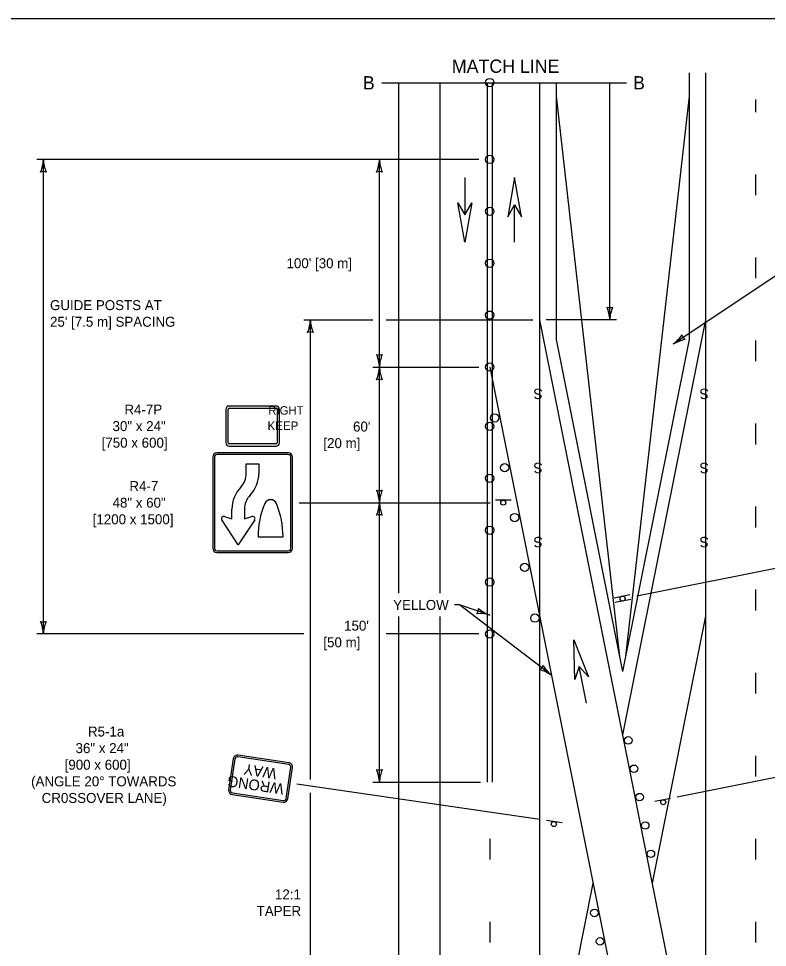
# Model space of a CAD drawing. Extents: x 49991.4 to 50021, y 49987.6 to 50011.4.
# Drawn here: x 50003.75 to 50008.26, y 49993.41 to 49999 of the extents above; entities that cross this region are included whole.
import ezdxf

# ---------------------------------------------------------------- set-up
doc = ezdxf.new("R2010")
doc.units = 0
for name, color, linetype in [('Level 1', 7, 'Continuous'), ('Level 2', 7, 'Continuous'), ('Level 3', 7, 'Continuous'), ('Level 6', 7, 'Continuous')]:
    doc.layers.add(name, color=color, linetype=linetype)

msp = doc.modelspace()

# ---------------------------------------------------------------- linework, layer by layer
at = {"layer": 'Level 1'}
for p, q in [((50007.7852, 49998.6725), (50007.7852, 49997.0679)), ((50007.8852, 49998.6725), (50007.8852, 49997.1857)), ((50006.0352, 49998.6125), (50006.0352, 49995.5387)), ((50006.2852, 49998.6125), (50006.2852, 49995.5387)), ((50006.5702, 49998.6125), (50006.5702, 49998.1511)), ((50006.6002, 49998.6125), (50006.6002, 49998.1511)), ((50006.8852, 49998.6125), (50006.8852, 49997.1857)), ((50006.9852, 49998.6125), (50006.9852, 49997.0679)), ((50006.9852, 49998.5323), (50007.3672, 49995.1581)), ((50007.7852, 49998.5323), (50007.4032, 49995.1581)), ((50008.1852, 49998.5125), (50008.1852, 49998.4357)), ((50006.5702, 49998.1511), (50006.5702, 49994.4011)), ((50006.6002, 49998.1511), (50006.6002, 49994.4011)), ((50006.4351, 49998.0424), (50006.4351, 49997.8166)), ((50006.4353, 49998.0424), (50006.4353, 49997.8166)), ((50008.1852, 49998.0607), (50008.1852, 49997.9357)), ((50006.735, 49997.6524), (50006.735, 49997.8782)), ((50006.7352, 49997.6524), (50006.7352, 49997.8782)), ((50008.1852, 49997.5607), (50008.1852, 49997.4357)), ((50006.8852, 49997.1857), (50006.8852, 49995.4011)), ((50006.8852, 49997.1855), (50008.1852, 49990.6855)), ((50007.8852, 49997.1857), (50007.3852, 49994.6857)), ((50007.8852, 49997.1857), (50007.8852, 49995.4012)), ((50006.9852, 49997.0679), (50007.3852, 49995.0679)), ((50007.7852, 49997.0679), (50007.3852, 49995.0679)), ((50008.1852, 49997.0607), (50008.1852, 49996.9357)), ((50006.5852, 49996.9011), (50007.8852, 49990.4009)), ((50004.9959, 49996.6463), (50004.9959, 49996.4447)), ((50005.0094, 49996.4447), (50005.0094, 49996.6463)), ((50005.2983, 49996.6665), (50005.0161, 49996.6665)), ((50005.0161, 49996.653), (50005.2983, 49996.653)), ((50005.305, 49996.6463), (50005.305, 49996.4447)), ((50005.3185, 49996.4447), (50005.3185, 49996.6463)), ((50008.1852, 49996.5607), (50008.1852, 49996.4357)), ((50005.2983, 49996.438), (50005.0161, 49996.438)), ((50005.0161, 49996.4245), (50005.2983, 49996.4245)), ((50004.9172, 49996.3595), (50004.9172, 49995.8095)), ((50004.9272, 49996.3595), (50004.9272, 49995.8095)), ((50005.3722, 49996.3845), (50004.9422, 49996.3845)), ((50005.3722, 49996.3745), (50004.9422, 49996.3745)), ((50005.3872, 49995.8095), (50005.3872, 49996.3595)), ((50005.3972, 49995.8095), (50005.3972, 49996.3595)), ((50005.1192, 49996.2609), (50005.1192, 49996.3175)), ((50005.1192, 49996.3175), (50005.1948, 49996.3175)), ((50005.1948, 49996.3175), (50005.1948, 49996.2609)), ((50006.7151, 49996.0997), (50006.6191, 49996.0997)), ((50008.1852, 49996.0607), (50008.1852, 49995.9357)), ((50004.9888, 49996.0017), (50005.0332, 49995.9881)), ((50005.0332, 49995.9881), (50005.0332, 49996.0455)), ((50005.1084, 49996.0455), (50005.1084, 49995.9881)), ((50005.1084, 49995.9881), (50005.1526, 49996.0017)), ((50005.0704, 49995.8313), (50004.9716, 49995.9805)), ((50005.17, 49995.9805), (50005.0704, 49995.8313)), ((50005.1696, 49995.9805), (50005.17, 49995.9805)), ((50005.1904, 49995.8779), (50005.341, 49995.8779)), ((50004.9422, 49995.7945), (50005.3722, 49995.7945)), ((50004.9422, 49995.7845), (50005.3722, 49995.7845)), ((50006.8852, 49995.7763), (50006.8852, 49995.6513)), ((50008.1852, 49995.5607), (50008.1852, 49995.4357)), ((50007.3351, 49995.5122), (50007.4293, 49995.531)), ((50007.4352, 49995.5012), (50007.341, 49995.4827)), ((50006.0352, 49995.3987), (50006.0352, 49988.1255)), ((50006.2852, 49995.3987), (50006.2852, 49988.1255)), ((50006.8852, 49995.4011), (50006.8852, 49992.1858)), ((50007.8852, 49995.4012), (50007.5636, 49993.7933)), ((50007.8852, 49995.4012), (50007.8852, 49992.1855)), ((50007.1685, 49994.8766), (50007.1243, 49995.0981)), ((50007.1687, 49994.8766), (50007.1245, 49995.0982)), ((50008.1852, 49995.0607), (50008.1852, 49994.9357)), ((50005.0412, 49994.5431), (50005.0132, 49994.3551)), ((50005.3748, 49994.5083), (50005.0682, 49994.5543)), ((50005.3762, 49994.5183), (50005.0696, 49994.5641)), ((50008.1852, 49994.5607), (50008.1852, 49994.4357)), ((50005.0512, 49994.5417), (50005.023, 49994.3537)), ((50005.3592, 49994.3035), (50005.3874, 49994.4913)), ((50005.3692, 49994.3019), (50005.3972, 49994.4899)), ((50005.0342, 49994.3267), (50005.3408, 49994.2809)), ((50005.0356, 49994.3367), (50005.3422, 49994.2909)), ((50007.5803, 49994.2865), (50007.6745, 49994.305)), ((50007.0211, 49994.157), (50006.9261, 49994.1712)), ((50006.5852, 49994.0607), (50006.5852, 49993.9357)), ((50008.1852, 49994.0607), (50008.1852, 49993.9357)), ((50007.2067, 49993.7934), (50006.8852, 49992.1858)), ((50006.5852, 49993.5607), (50006.5852, 49993.4357)), ((50008.1852, 49993.5607), (50008.1852, 49993.4357))]:
    msp.add_line(p, q, dxfattribs=at)
for points in [[(49999.3835, 49998.9992), (50016.7501, 49998.9992), (50016.7501, 49987.7988), (49999.3835, 49987.7988)], [(50006.777, 49997.806), (50006.7352, 49998.0424), (50006.6934, 49997.806), (50006.7352, 49997.878)], [(50006.4771, 49997.8888), (50006.4353, 49997.6524), (50006.3935, 49997.8888), (50006.4353, 49997.8168)], [(50007.0973, 49995.0191), (50007.0919, 49995.2592), (50007.1793, 49995.0354), (50007.1243, 49995.0979)]]:
    msp.add_lwpolyline(points, close=True, dxfattribs=at)
for points in [[(50005.2878, 49996.0951), (50005.2956, 49996.0875)], [(50005.0712, 49995.8313), (50005.0702, 49995.8325)]]:
    msp.add_lwpolyline(points, dxfattribs=at)
for centre, radius in [((50006.5852, 49998.6139), 0.025), ((50006.5852, 49998.1511), 0.025), ((50006.5852, 49997.8386), 0.025), ((50006.5852, 49997.5261), 0.025), ((50006.5851, 49997.2135), 0.025), ((50006.5852, 49996.9011), 0.025), ((50006.6153, 49996.5951), 0.025), ((50006.5851, 49996.5438), 0.025), ((50006.6753, 49996.2951), 0.025), ((50006.5851, 49996.2313), 0.025), ((50006.6669, 49996.0845), 0.0152), ((50006.7353, 49995.9951), 0.025), ((50006.5851, 49995.9188), 0.025), ((50006.7953, 49995.6951), 0.025), ((50006.5851, 49995.6063), 0.025), ((50007.3852, 49995.5067), 0.0152), ((50006.857, 49995.3893), 0.025), ((50006.5851, 49995.2938), 0.025), ((50007.4196, 49994.6532), 0.0225), ((50007.4537, 49994.4824), 0.0225), ((50007.4877, 49994.3117), 0.0225), ((50007.6303, 49994.281), 0.0152), ((50006.9713, 49994.1492), 0.0152), ((50007.5217, 49994.141), 0.0225), ((50007.5557, 49993.9703), 0.0225), ((50007.2154, 49993.6143), 0.0225), ((50007.2494, 49993.4434), 0.0225)]:
    msp.add_circle(centre, radius, dxfattribs=at)
for centre, radius, start, end in [((50005.0161, 49996.6463), 0.0202, 90, 180), ((50005.0161, 49996.6463), 0.00672, 90, 180), ((50005.2983, 49996.6463), 0.0202, 360, 90), ((50005.2983, 49996.6463), 0.00672, 360, 90), ((50005.0161, 49996.4447), 0.0202, 180, 270), ((50005.0161, 49996.4447), 0.00672, 180, 270), ((50005.2983, 49996.4447), 0.00672, 270, 360), ((50005.2983, 49996.4447), 0.0202, 270, 360), ((50004.9421, 49996.3595), 0.025, 90, 180), ((50004.9421, 49996.3595), 0.015, 90, 180), ((50005.3721, 49996.3595), 0.025, 0, 90), ((50005.3721, 49996.3595), 0.015, 0, 90), ((50004.9421, 49995.8095), 0.025, 180, 270), ((50004.9421, 49995.8095), 0.015, 180, 270), ((50005.3721, 49995.8095), 0.025, 270, 0), ((50005.3721, 49995.8095), 0.015, 270, 0), ((50005.0659, 49994.5394), 0.025, 81.4987, 171.4987), ((50005.0659, 49994.5394), 0.015, 81.4987, 171.4987), ((50005.3725, 49994.4936), 0.015, 351.4987, 81.4987), ((50005.3725, 49994.4936), 0.025, 351.4987, 81.4987), ((50005.0379, 49994.3515), 0.025, 171.4987, 261.4987), ((50005.0379, 49994.3515), 0.015, 171.4987, 261.4987), ((50005.3444, 49994.3057), 0.025, 261.4987, 351.4987), ((50005.3444, 49994.3057), 0.015, 261.4987, 351.4987)]:
    msp.add_arc(centre, radius, start, end, dxfattribs=at)
for centre, major_axis, start_param, end_param in [((50004.9875, 49996.2608), (-0.1319, 0), 2.411875, 3.141593), ((50004.9875, 49996.2608), (-0.2073, 0), 2.411875, 3.141593), ((50005.2403, 49996.0456), (-0.2073, 0), 5.553465, 6.283185), ((50005.2403, 49996.0456), (-0.1319, 0), 5.553465, 6.283185), ((50005.7553, 49995.8801), (-0.5653, 0), 5.90292, 6.286763), ((50005.2654, 49996.0665), (-0.0377, 0), 3.521859, 5.902934), ((50004.7755, 49995.8801), (-0.5653, 0), 3.138019, 3.521863), ((50004.9844, 49995.988), (0.0149, 0), 1.263276, 3.704354), ((50005.1571, 49995.988), (0.0149, 0), 5.720439, 8.161485)]:
    msp.add_ellipse(centre, major_axis=major_axis, ratio=0.951905, start_param=start_param, end_param=end_param, dxfattribs=at)
at = {"layer": 'Level 3'}
for p, q in [((50007.3082, 49997.1857), (50007.3082, 49998.6125)), ((50006.5202, 49998.1511), (50003.8575, 49998.1511)), ((50003.8975, 49995.2938), (50003.8975, 49998.1511)), ((50005.9212, 49996.9011), (50005.9212, 49998.1511)), ((50008.912, 49997.8523), (50007.6889, 49997.0383)), ((50005.4652, 49997.1857), (50005.8812, 49997.1857)), ((50005.5052, 49996.0845), (50005.5052, 49997.1857)), ((50005.9612, 49997.1857), (50006.8452, 49997.1857)), ((50007.3482, 49997.1857), (50006.9252, 49997.1857)), ((50005.8812, 49996.9011), (50006.5202, 49996.9011)), ((50005.9212, 49996.0845), (50005.9212, 49996.9011)), ((50005.4372, 49996.0845), (50006.5872, 49996.0845)), ((50005.5052, 49994.418), (50005.5052, 49996.0845)), ((50005.9212, 49995.2938), (50005.9212, 49996.0845)), ((50007.4715, 49995.524), (50009.1861, 49995.8669)), ((50006.4037, 49995.4687), (50006.3721, 49995.4687)), ((50006.9563, 49995.0457), (50006.4037, 49995.4687)), ((50006.5853, 49995.4078), (50006.4037, 49995.4687)), ((50005.4652, 49995.2938), (50003.8575, 49995.2938)), ((50005.9212, 49994.4011), (50005.9212, 49995.2938)), ((50006.5201, 49995.2938), (50005.9612, 49995.2938)), ((50007.7137, 49994.3132), (50009.5739, 49994.6854)), ((50006.8865, 49994.1771), (50005.4228, 49994.39)), ((50005.8812, 49994.4011), (50006.5302, 49994.4011)), ((50005.5052, 49990.4015), (50005.5052, 49994.338))]:
    msp.add_line(p, q, dxfattribs=at)
for centre, radius, start, end in [((50003.6753, 49998.1603), 0.2223, 337.456, 357.6395), ((50004.1302, 49998.1626), 0.233, 182.8273, 202.0772), ((50005.699, 49998.1603), 0.2223, 337.456, 357.6395), ((50006.1539, 49998.1626), 0.233, 182.8273, 202.0772), ((50003.8975, 49998.0229), 0.0548, 72.1388, 107.8612), ((50005.9212, 49998.0229), 0.0548, 72.1388, 107.8612), ((50007.3082, 49997.3139), 0.0548, 252.1388, 287.8612), ((50007.0755, 49997.1742), 0.233, 2.8273, 22.0772), ((50007.5303, 49997.1765), 0.2223, 157.456, 177.6395), ((50005.2831, 49997.1949), 0.2223, 337.456, 357.6395), ((50005.7379, 49997.1972), 0.233, 182.8273, 202.0772), ((50005.5052, 49997.0575), 0.0548, 72.1388, 107.8612), ((50007.5504, 49997.2257), 0.233, 306.4719, 325.7218), ((50007.8043, 49996.8483), 0.2223, 101.1007, 121.2842), ((50007.7956, 49997.1093), 0.0548, 195.7835, 231.5058), ((50005.9212, 49997.0293), 0.0548, 252.1388, 287.8612), ((50005.6885, 49996.8896), 0.233, 2.8273, 22.0772), ((50006.1433, 49996.8919), 0.2223, 157.456, 177.6395), ((50005.699, 49996.9103), 0.2223, 337.456, 357.6395), ((50006.1539, 49996.9126), 0.233, 182.8273, 202.0772), ((50005.9212, 49996.7729), 0.0548, 72.1388, 107.8612), ((50005.9212, 49996.2128), 0.0548, 252.1388, 287.8612), ((50005.6885, 49996.073), 0.233, 2.8273, 22.0772), ((50006.1433, 49996.0754), 0.2223, 157.456, 177.6395), ((50005.699, 49996.0937), 0.2223, 337.456, 357.6395), ((50006.1539, 49996.096), 0.233, 182.8273, 202.0772), ((50005.9212, 49995.9563), 0.0548, 72.1388, 107.8612), ((50006.4637, 49995.4486), 0.0548, 323.5785, 359.3009), ((50006.6647, 49995.6154), 0.2223, 228.8957, 249.0792), ((50006.5221, 49995.1835), 0.233, 74.267, 93.5168), ((50003.8975, 49995.422), 0.0548, 252.1388, 287.8612), ((50003.6648, 49995.2823), 0.233, 2.8273, 22.0772), ((50004.1196, 49995.2846), 0.2223, 157.456, 177.6395), ((50006.8545, 49995.1236), 0.0548, 304.6999, 340.4222), ((50007.0986, 49995.2165), 0.2223, 210.0171, 230.2006), ((50006.8239, 49994.8539), 0.233, 55.3884, 74.6382), ((50005.9212, 49994.5293), 0.0548, 252.1388, 287.8612), ((50005.6885, 49994.3896), 0.233, 2.8273, 22.0772), ((50006.1433, 49994.3919), 0.2223, 157.456, 177.6395)]:
    msp.add_arc(centre, radius, start, end, dxfattribs=at)
at = {"layer": 'Level 6'}
msp.add_line((50005.9352, 49998.6125), (50007.4082, 49998.6125), dxfattribs=at)

# ---------------------------------------------------------------- texts
at = {"layer": 'Level 1'}
for s, height, rotation, p in [('S', 0.0625, 180, (50006.9044, 49996.7708)), ('S', 0.0625, 180, (50007.9044, 49996.7708)), ('RIGHT', 0.05095, 360, (50005.2522, 49996.6143)), ('KEEP', 0.05193, 360, (50005.2472, 49996.5215)), ('S', 0.0625, 180, (50006.9044, 49996.3246)), ('S', 0.0625, 180, (50007.9044, 49996.3246)), ('S', 0.0625, 180, (50006.9044, 49995.8784)), ('S', 0.0625, 180, (50007.9044, 49995.8785)), ('WAY', 0.065, 171.4987, (50005.3054, 49994.4833)), ('WRONG', 0.065, 171.4987, (50005.3486, 49994.3909))]:
    msp.add_text(s, height=height, rotation=rotation, dxfattribs=at).set_placement(p)
at = {"layer": 'Level 2'}
for s, height, p in [('MATCH LINE', 0.08, (50006.3571, 49998.6725)), ('B', 0.08, (50005.8212, 49998.5725)), ('B', 0.08, (50007.4482, 49998.5725)), ("100' [30 m]", 0.06, (50005.3617, 49997.4961)), ('GUIDE POSTS AT', 0.06, (50003.9375, 49997.2438)), ("25' [7.5 m] SPACING", 0.06, (50003.9375, 49997.1438)), ('R4-7P', 0.06, (50004.3856, 49996.6155)), ('30" x 24"', 0.06, (50004.3141, 49996.5155)), ("60'", 0.06, (50005.7623, 49996.5128)), ('[750 x 600]', 0.06, (50004.2485, 49996.4155)), ('[20 m]', 0.06, (50005.5834, 49996.4128)), ('R4-7', 0.06, (50004.4156, 49996.1545)), ('48" x 60"', 0.06, (50004.3141, 49996.0545)), ('[1200 x 1500]', 0.06, (50004.1946, 49995.9545)), ("150'", 0.06, (50005.7084, 49995.3138)), ('[50 m]', 0.06, (50005.5834, 49995.2138)), ('R5-1a', 0.06, (50004.1661, 49994.6766)), ('36" x 24"', 0.06, (50004.0913, 49994.5766)), ('[900 x 600]', 0.06, (50004.0258, 49994.4766)), ('(ANGLE 20° TOWARDS', 0.06, (50003.8236, 49994.3766)), ('CR0SSOVER LANE)', 0.06, (50003.8873, 49994.2766)), ('12:1', 0.06, (50005.292, 49993.6959)), ('TAPER', 0.06, (50005.1818, 49993.5959))]:
    msp.add_text(s, height=height, dxfattribs=at).set_placement(p)
msp.add_text('YELLOW', height=0.06, rotation=360, dxfattribs=at).set_placement((50006.0039, 49995.4387))

doc.saveas('drawing.dxf')
